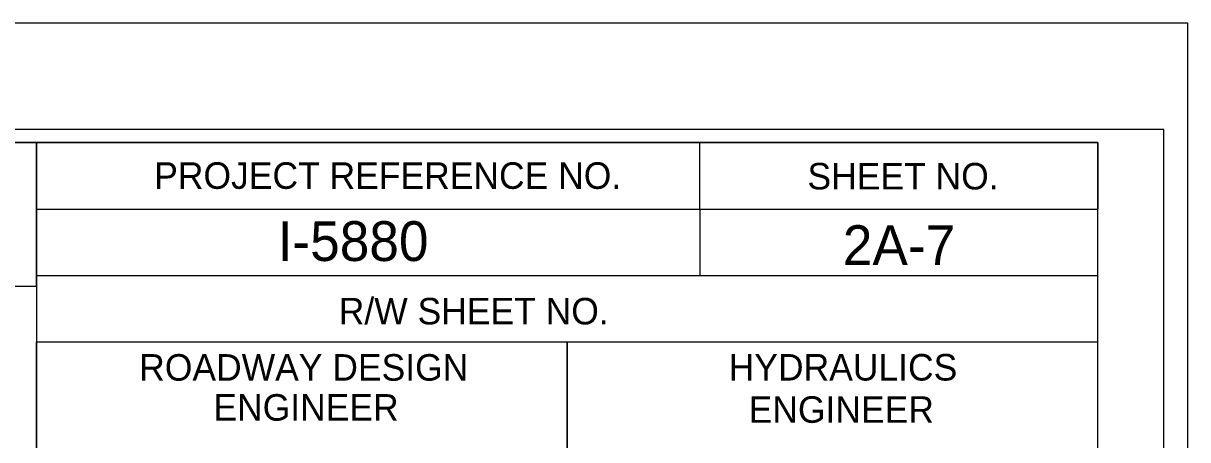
# Model space of a CAD drawing. Extents: x 1640342 to 1730599, y 538663 to 843747.
# Drawn here: x 1730133.49 to 1730177.39, y 538866.52 to 538882.22 of the extents above; entities that cross this region are included whole.
import ezdxf

# ---------------------------------------------------------------- set-up
doc = ezdxf.new("R2010")
doc.units = 0
for name, color, linetype in [('Prop Dimension Text', 7, 'Continuous'), ('Sheet Data Field CELL', 7, 'Continuous'), ('Sheet Plan CELL', 7, 'Continuous'), ('Sheet Plot Border Inside CELL', 7, 'Continuous'), ('Sheet Plot Border Outside CELL', 7, 'Continuous')]:
    doc.layers.add(name, color=color, linetype=linetype)

msp = doc.modelspace()

# ---------------------------------------------------------------- linework, layer by layer
at = {"layer": 'Prop Dimension Text'}
msp.add_lwpolyline([(1730104.001, 538872.31), (1730133.983, 538872.31), (1730133.983, 538877.721), (1730104.001, 538877.721)], close=True, dxfattribs=at)
at = {"layer": 'Sheet Plan CELL'}
for p, q in [((1730158.985, 538877.706), (1730158.995, 538872.706)), ((1730133.98, 538875.211), (1730173.99, 538875.208)), ((1730133.983, 538872.703), (1730173.99, 538872.708)), ((1730133.983, 538872.703), (1730173.99, 538872.708)), ((1730133.983, 538872.703), (1730133.983, 538870.206)), ((1730153.993, 538870.206), (1730153.995, 538847.713))]:
    msp.add_line(p, q, dxfattribs=at)
for points in [[(1729873.99, 538667.718), (1729873.985, 538877.713), (1730133.983, 538877.721), (1730133.985, 538847.708), (1730173.993, 538847.706), (1730173.993, 538667.718)], [(1730173.998, 538877.718), (1729873.99, 538877.718), (1729873.99, 538667.718), (1730173.993, 538667.718)], [(1730133.983, 538877.721), (1730173.998, 538877.718), (1730173.99, 538872.708), (1730133.983, 538872.703)], [(1730133.983, 538870.206), (1730153.993, 538870.206), (1730153.993, 538847.703), (1730133.985, 538847.708)], [(1730153.993, 538870.206), (1730173.99, 538870.208), (1730173.993, 538847.706), (1730153.993, 538847.703)]]:
    msp.add_lwpolyline(points, close=True, dxfattribs=at)
at = {"layer": 'Sheet Plot Border Inside CELL'}
msp.add_lwpolyline([(1729843.293, 538667.216), (1730176.49, 538667.218), (1730176.493, 538878.216), (1729843.293, 538878.216)], close=True, dxfattribs=at)
at = {"layer": 'Sheet Plot Border Outside CELL'}
msp.add_lwpolyline([(1729840.693, 538663.216), (1730177.393, 538663.216), (1730177.393, 538882.216), (1729840.693, 538882.216)], close=True, dxfattribs=at)

# ---------------------------------------------------------------- texts
at = {"layer": 'Sheet Data Field CELL'}
for s, p in [('I-5880', (1730143.079, 538873.256)), ('2A-7', (1730164.388, 538873.103))]:
    msp.add_text(s, height=1.5, rotation=0, dxfattribs=at).set_placement(p)
at = {"layer": 'Sheet Plan CELL'}
for s, height, p in [('PROJECT REFERENCE NO.', 1.00002, (1730138.423, 538875.976)), ('SHEET NO.', 1, (1730163.055, 538875.953)), ('R/W SHEET NO.', 1.00002, (1730145.383, 538870.866)), ('ROADWAY DESIGN', 1.00002, (1730137.858, 538868.746)), ('HYDRAULICS', 1, (1730160.085, 538868.751)), ('ENGINEER', 1, (1730140.655, 538867.238)), ('ENGINEER', 1, (1730160.838, 538867.158))]:
    msp.add_text(s, height=height, rotation=0, dxfattribs=at).set_placement(p)

doc.saveas('drawing.dxf')
